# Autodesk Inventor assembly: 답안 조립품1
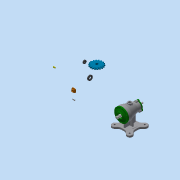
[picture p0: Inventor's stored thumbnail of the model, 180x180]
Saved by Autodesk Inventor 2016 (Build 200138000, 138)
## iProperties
Created: 2018-03
Part Number: 답안 조립품1
Material: 일반
Document SubType Name: Assembly
Designer: 605-15
Author: 605-15
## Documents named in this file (15)
- C:\Users\605-15\Desktop\480307V1005\답안 조립품1.iam
- C:\Users\605-15\Desktop\480307V1005\본체.ipt
- C:\Users\605-15\Desktop\480307V1005\480307V1005\뒤커버.ipt
- C:\Users\605-15\Desktop\480307V1005\480307V1005\마개.ipt
- C:\Users\605-15\Desktop\480307V1005\480307V1005\베어링-6200.ipt
- C:\Users\605-15\Desktop\480307V1005\480307V1005\베어링-6203.ipt
- C:\Users\605-15\Desktop\480307V1005\480307V1005\볼트 M4 x 12.ipt
- 볼트 M4 x 12.ipt
- C:\Users\605-15\Desktop\480307V1005\480307V1005\스프로킷.ipt
- C:\Users\605-15\Desktop\480307V1005\480307V1005\앞커버.ipt
- C:\Users\605-15\Desktop\480307V1005\480307V1005\오일 실 10 20 7.ipt
- C:\Users\605-15\Desktop\480307V1005\480307V1005\오일 실 17 30 8.ipt
- C:\Users\605-15\Desktop\480307V1005\480307V1005\축.ipt
- C:\Users\605-15\Desktop\480307V1005\480307V1005\키 5 x 5.ipt
- 키 5 x 5.ipt
